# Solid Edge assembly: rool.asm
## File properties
Author: Mac
Template: Normal.asm
Last saved by: Mac
Revision: 3
Application: Solid Edge
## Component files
pump.par
rooliratas.par
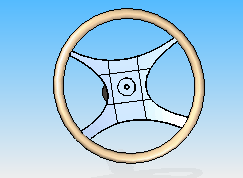
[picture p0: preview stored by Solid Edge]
